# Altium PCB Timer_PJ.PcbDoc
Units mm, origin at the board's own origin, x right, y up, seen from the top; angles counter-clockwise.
Board outline 77 x 46 mm, 2 copper layers (Top Layer, Bottom Layer); 19 components, 12 nets, 42 pads, 0 vias.
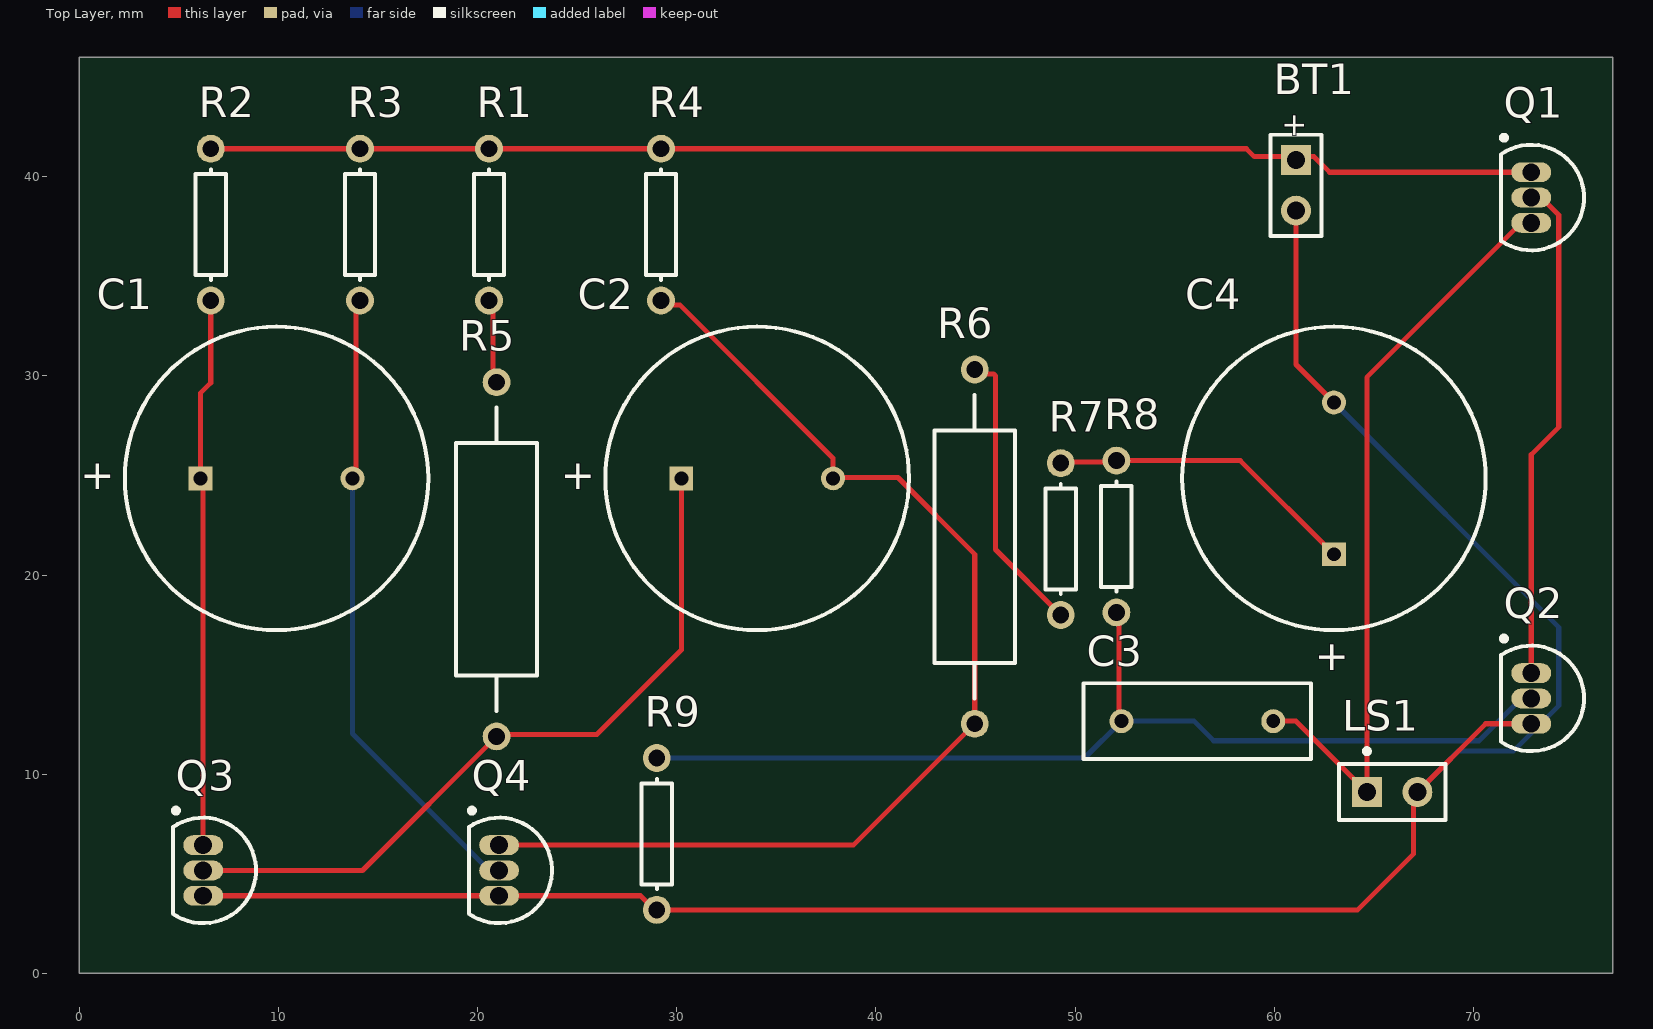
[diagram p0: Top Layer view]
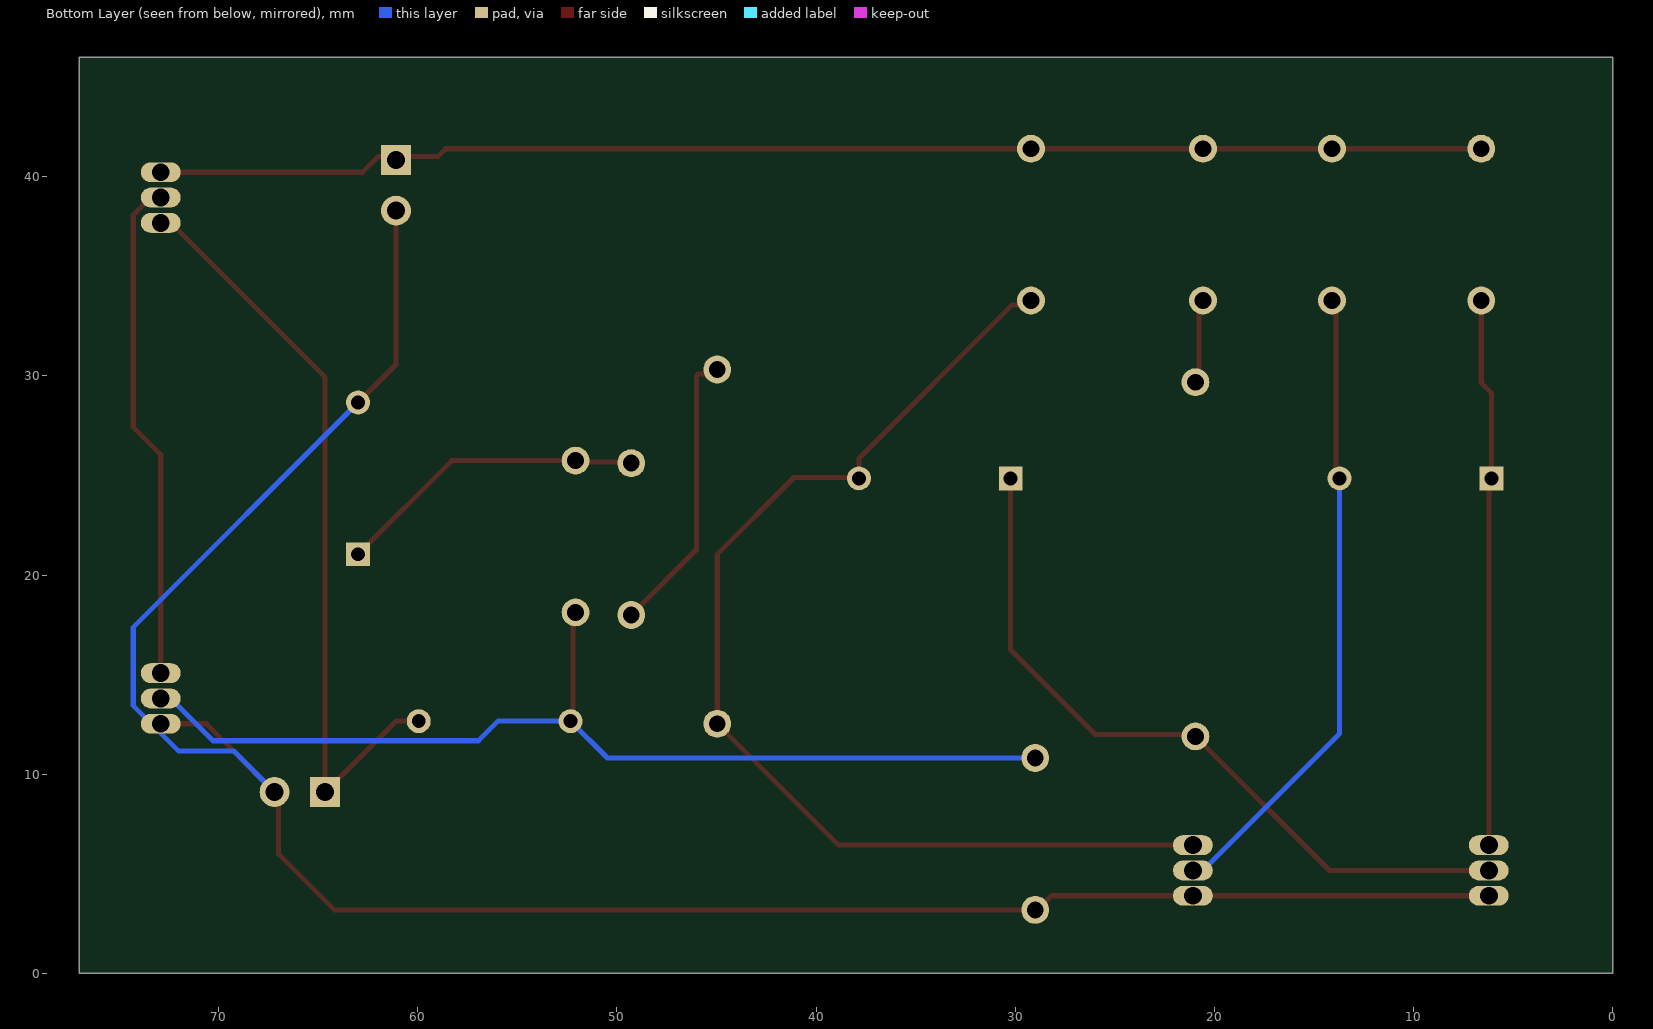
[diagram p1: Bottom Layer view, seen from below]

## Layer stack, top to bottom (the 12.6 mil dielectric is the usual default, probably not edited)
Top Solder: solder mask 0.0102, Solder Resist, Dk 3.5
Top Layer: signal copper 0.0356
Dielectric 1: dielectric 0.32, FR-4, Dk 4.8
Bottom Layer: signal copper 0.0356
Bottom Solder: solder mask 0.0102, Solder Resist, Dk 3.5

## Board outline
0,0 77,0 77,46 0,46

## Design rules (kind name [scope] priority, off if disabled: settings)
Clearance [All] p1: gap=0.254 ignorepadtopadclearanceinfootprint=FALSE except(0: Arc-Hole Track-Hole SMDPad-Hole THPad-Hole Via-Hole Fill-Hole Poly-Hole Region-Hole Text-Hole)
PolygonConnect [All] p1: connectstyle=Relief reliefconductorwidth=0.254 reliefentries=4 polygonreliefangle="90 Angle" airgapwidth=0.254
RoutingVias [All] p1: holewidth=0.711 width=1.27 viastyle="Through Hole" minholewidth=0.711 minwidth=1.27 maxholewidth=0.711 maxwidth=1.27
SolderMaskExpansion [All] p1: expansion=0.102 istentingtop=FALSE
Width [All] p1: maxlimit=0.254 minlimit=0.254 preferedwidth=0.254
30 further rules are at their usual default settings.

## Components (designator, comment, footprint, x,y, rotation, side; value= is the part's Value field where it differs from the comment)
BT1 "Battery" BAT-2 61.092,39.563 r270 top
C1 "Cap Pol1" RB7.6-15 9.911,24.853 r180 top value=220uF
C2 "Cap Pol1" RB7.6-15 34.041,24.853 r180 top value=220uF
C3 "Cap" RAD-0.3 56.139,12.661 r0 top value=0.02uF
C4 "Cap Pol1" RB7.6-15 62.997,24.853 r270 top value=220uF
LS1 "Speaker" PIN2 64.648,9.105 r0 top
Q1 "NPN" TO-226-AA 72.903,38.95 r180 top
Q2 "NPN" TO-226-AA 72.903,13.804 r180 top
Q3 "NPN" TO-226-AA 6.228,5.168 r180 top
Q4 "NPN" TO-226-AA 21.087,5.168 r180 top
R1 "Res1" AXIAL-0.3 20.579,37.591 r270 top value=4.7K
R2 "Res1" AXIAL-0.3 6.609,37.591 r270 top value=3.9K
R3 "Res1" AXIAL-0.3 14.102,37.591 r270 top value=10K
R4 "Res1" AXIAL-0.3 29.215,37.591 r270 top value=3.9K
R5 "Res Adj1" AXIAL-0.7 20.96,20.789 r270 top value=47K
R6 "Res Adj1" AXIAL-0.7 44.963,21.424 r90 top value=100K
R7 "Res1" AXIAL-0.3 49.281,21.805 r270 top value=10K
R8 "Res1" AXIAL-0.3 52.075,21.932 r90 top value=100K
R9 "Res1" AXIAL-0.3 29,7 r270 top value=47K

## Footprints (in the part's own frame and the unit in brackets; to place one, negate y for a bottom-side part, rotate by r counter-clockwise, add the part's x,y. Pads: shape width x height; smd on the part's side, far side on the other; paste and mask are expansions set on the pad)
AXIAL-0.3 [mm] "Axial Device, Thru-Hole; 2 Leads; 0.3 in Pin Spacing"
  round 1.4 hole 0.85: 1(-3.81,0) 2(3.81,0)
  silkscreen extent -2.77,-0.76 2.77,0.76
AXIAL-0.7 [mm] "Axial Device, Thru-Hole; 2 Leads; 0.7 in Pin Spacing"
  round 1.4 hole 0.85: 1(-8.89,0) 2(8.89,0)
  silkscreen extent -7.62,-2.03 7.62,2.03
BAT-2 [mm] "Battery; 2 Leads"
  rect 1.5x1.5 hole 0.9: 1(-1.27,0)
  round 1.5 hole 0.9: 2(1.27,0)
  silkscreen extent -2.54,-1.27 2.54,1.27
PIN2 [mm] "Photosensitive Diode; 2 Leads"
  rect 1.5x1.5 hole 0.9: 1(0,0)
  round 1.5 hole 0.9: 2(2.54,0)
  silkscreen extent -1.4,-1.4 3.94,2.17
RAD-0.3 [mm] "Radial Cap, Thru-Hole; 2 Leads; 0.3 in Pin Spacing"
  round 1.2 hole 0.7: 1(-3.81,0) 2(3.81,0)
  silkscreen extent -5.71,-1.91 5.71,1.91
RB7.6-15 [mm] "Polarized Capacitor (Radial); 2 Leads"
  rect 1.2x1.2 hole 0.7: 1(3.81,0)
  round 1.2 hole 0.7: 2(-3.81,0)
  silkscreen extent -7.62,-7.62 7.62,7.62
TO-226-AA [mm] "TO, Flat Index; 3 In-Line, Axial Leads; Body Dia. 4.8mm; Leads 0.55 x 0.51 mm (max)"
  oval 2x1 hole 0.9: 1(0,-1.27) 2(0,0) 3(0,1.27)
  silkscreen extent -2.65,-3.13 1.52,2.65, body extent -2.65,-2.66 1.52,2.66, height 5.33

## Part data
BT1: "Multicell Battery"
C1 C2 C4: "Polarized Capacitor (Radial)"
C3: "Capacitor"
LS1: "Loudspeaker"
Q1 Q2 Q3 Q4: "NPN Bipolar Transistor"
R1 R2 R3 R4 R7 R8 R9: "Resistor"
R5 R6: "Variable Resistor"

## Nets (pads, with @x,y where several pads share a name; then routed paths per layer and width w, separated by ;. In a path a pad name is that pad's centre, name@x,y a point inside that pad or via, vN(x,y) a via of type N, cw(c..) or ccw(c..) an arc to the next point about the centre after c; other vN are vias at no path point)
GND: BT1.2 C4.2 LS1.2 Q2.3 Q3.3 Q4.3 R9.2 | length 111.8
  Top Layer w0.254: Q3.3 Q4.3 28.179,3.898 28.887,3.19 R9.2 64.19,3.19 67,6 67,8.917 LS1.2 70.617,12.534 Q2.3 ; BT1.2 61.092,30.568 C4.2
  Bottom Layer w0.254: C4.2 74.284,17.376 74.284,13.439 72.017,11.172 69.255,11.172 LS1.2
NetC1_1: C1.1 Q3.1 R2.2 | length 28.1
  Top Layer w0.254: Q3.1 6.228,24.726 C1.1 6.101,29.145 6.609,29.653 R2.2 6.781,33.781 R2.2@7,34
NetC1_2: C1.2 Q4.2 R3.2 | length 32.1
  Top Layer w0.254: C1.2 13.902,25.034 13.902,33.581 R3.2
  Bottom Layer w0.254: C1.2 13.721,12.034 20.587,5.168 Q4.2
NetC2_1: C2.1 Q3.2 R5.2 | length 37.2
  Top Layer w0.254: Q3.2 14.229,5.168 R5.2 21.061,12 26,12 30.231,16.231 C2.1
NetC2_2: C2.2 Q4.1 R4.2 R6.1 | length 56.6
  Top Layer w0.254: Q4.1 38.867,6.438 R6.1 44.963,21.037 41.105,24.895 37.893,24.895 C2.2 37.851,25.864 30.153,33.562 29.434,33.562 R4.2
NetC3_1: C3.1 Q2.2 R8.1 R9.1 | length 51.5
  Top Layer w0.254: R8.1 52.202,17.995 52.202,12.788 C3.1
  Bottom Layer w0.254: R9.1 50.478,10.81 C3.1 55.98,12.661 56.961,11.68 70.279,11.68 72.403,13.804 Q2.2
NetC3_2: C3.2 LS1.1 Q1.3 | length 38.5
  Top Layer w0.254: C3.2 61.092,12.661 LS1.1 64.648,29.925 72.403,37.68 Q1.3
NetC4_1: C4.1 R7.1 R8.2 | length 15.7
  Top Layer w0.254: R7.1 49.345,25.678 52.012,25.678 R8.2 58.298,25.742 C4.1
NetQ1_2: Q1.2 Q2.1 | length 25.3
  Top Layer w0.254: Q2.1 72.903,26.041 74.284,27.422 74.284,38.069 73.403,38.95 Q1.2
NetR1_2: R1.2 R5.1 | length 4.3
  Top Layer w0.254: R1.2 20.77,33.591 20.77,29.869 R5.1
NetR6_2: R6.2 R7.2 | length 14.5
  Top Layer w0.254: R6.2 45.182,30.095 45.905,30.095 46,30 46,21.276 R7.2
VCC: BT1.1 Q1.1 R1.1 R2.1 R3.1 R4.1 | length 66.9
  Top Layer w0.254: R2.1 R3.1 R1.1 R4.1 58.599,41.401 59,41 60.925,41 BT1.1 61.259,41 62,41 62.78,40.22 Q1.1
